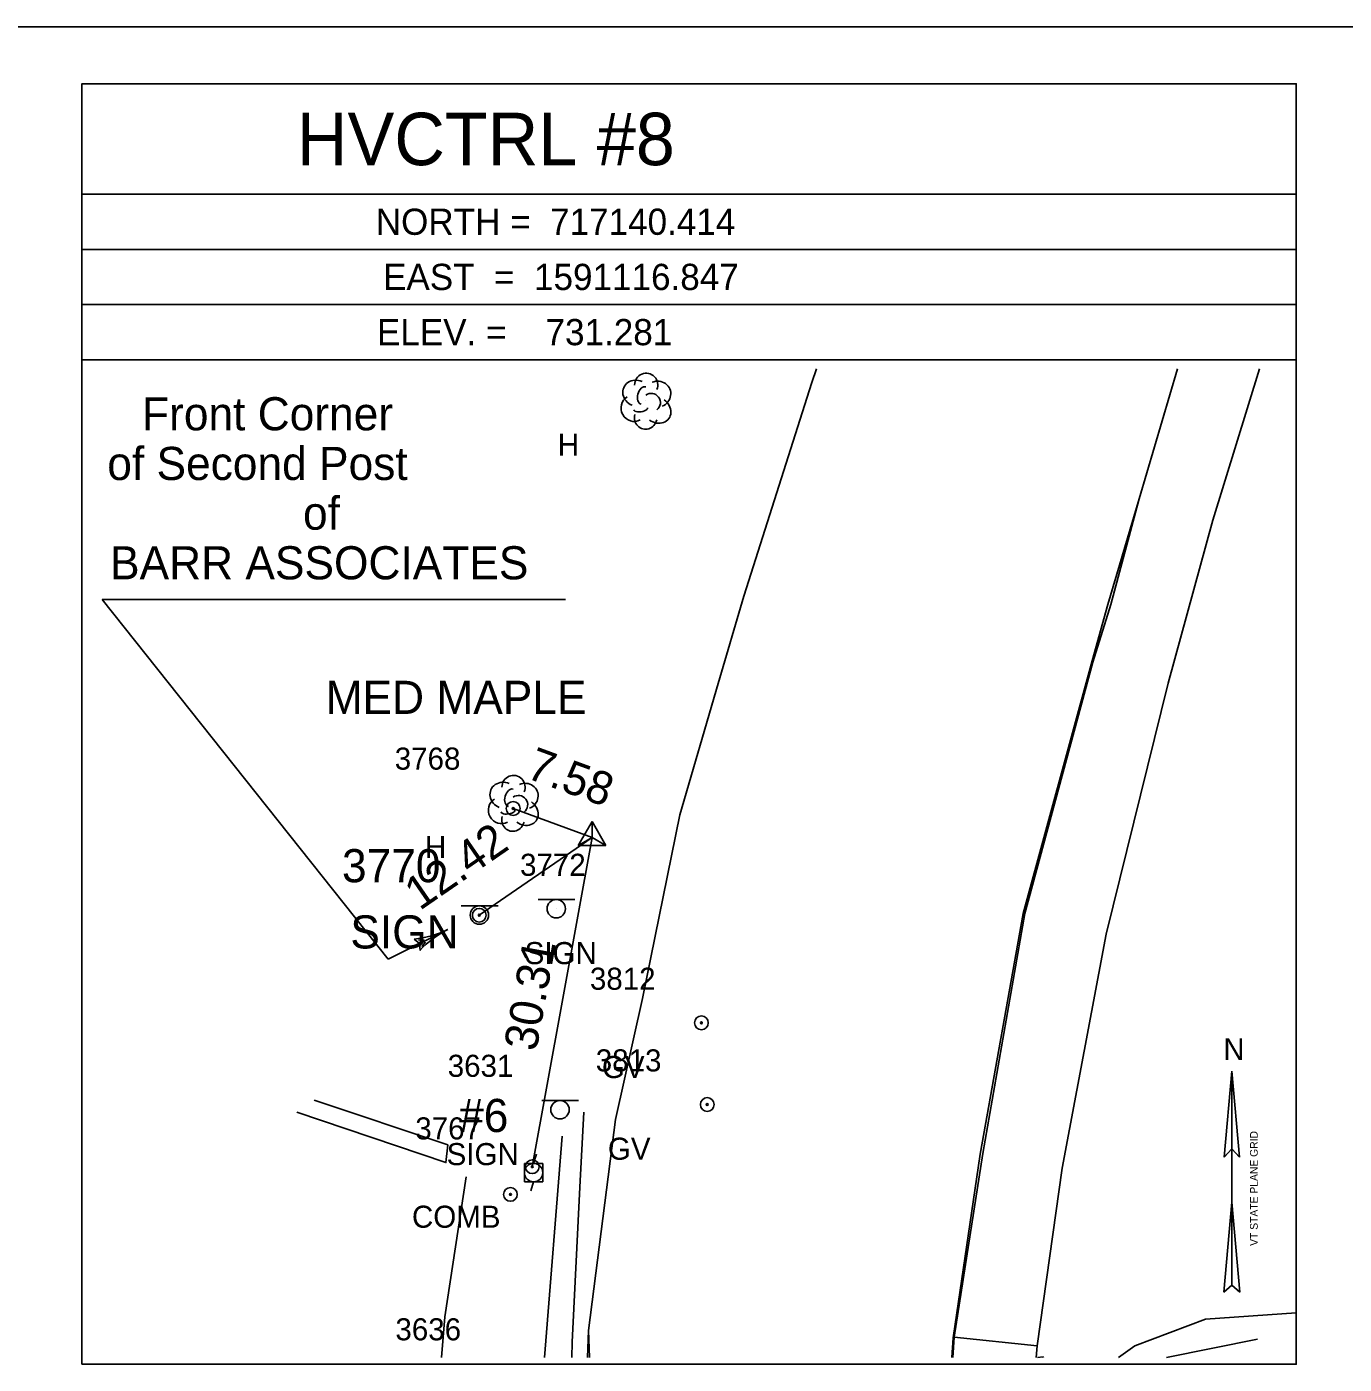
# Model space of a CAD drawing. Extents: x 1586965 to 1590952, y 716317 to 720029.
# Drawn here: x 1590582.2 to 1590701.5, y 716489.9 to 716611 of the extents above; entities that cross this region are included whole.
import ezdxf

# ---------------------------------------------------------------- set-up
doc = ezdxf.new("R2010")
doc.units = 0
for name, color, linetype in [('CBP', 7, 'Continuous'), ('CPSM', 7, 'Continuous'), ('Default', 7, 'Continuous'), ('L_A', 7, 'Continuous'), ('L_C', 7, 'Continuous'), ('L_I', 7, 'Continuous'), ('LAHR', 7, 'Continuous'), ('LAPB', 7, 'Continuous'), ('LTD', 7, 'Continuous'), ('LW', 7, 'Continuous'), ('MPIR', 7, 'Continuous'), ('NBL2', 7, 'Continuous'), ('NNA_P', 7, 'Continuous'), ('PET', 7, 'Continuous'), ('PSP', 7, 'Continuous'), ('RC', 7, 'Continuous'), ('RDG', 7, 'Continuous'), ('RDP', 7, 'Continuous'), ('RSW', 7, 'Continuous'), ('S_A', 7, 'Continuous'), ('S_C', 7, 'Continuous'), ('S_I', 7, 'Continuous'), ('SSGN', 7, 'Continuous'), ('U_A', 7, 'Continuous'), ('U_C', 7, 'Continuous'), ('U_I', 7, 'Continuous'), ('UP', 7, 'Continuous'), ('UWV', 7, 'Continuous')]:
    doc.layers.add(name, color=color, linetype=linetype)

msp = doc.modelspace()

# ---------------------------------------------------------------- linework, layer by layer
at = {"layer": 'CBP'}
for centre, radius in [((1590626.26, 716540.21), 0.625), ((1590626.26, 716540.21), 0.0833), ((1590623.19, 716530.54), 0.625), ((1590623.19, 716530.54), 0.0833), ((1590627.99, 716507.76), 0.625), ((1590627.99, 716507.76), 0.0833)]:
    msp.add_circle(centre, radius, dxfattribs=at)
at = {"layer": 'CPSM'}
for p, q in [((1590632.15, 716536.87), (1590633.4, 716539.03)), ((1590634.65, 716536.87), (1590633.4, 716539.03)), ((1590633.4, 716537.59), (1590633.4, 716539.03)), ((1590632.15, 716536.87), (1590633.4, 716537.59)), ((1590633.4, 716537.59), (1590633.4, 716537.59)), ((1590633.4, 716537.59), (1590634.65, 716536.87)), ((1590632.15, 716536.87), (1590634.65, 716536.87))]:
    msp.add_line(p, q, dxfattribs=at)
at = {"layer": 'Default'}
for p, q in [((1590630.99, 716559.15), (1590589.02, 716559.15)), ((1590589.02, 716559.15), (1590614.93, 716526.55)), ((1590626.26, 716540.21), (1590633.4, 716537.59)), ((1590633.4, 716537.59), (1590623.19, 716530.54)), ((1590633.4, 716537.59), (1590627.99, 716507.76)), ((1590614.93, 716526.55), (1590620.33, 716529.25)), ((1590617.3, 716528.38), (1590617.78, 716527.97)), ((1590617.67, 716528.29), (1590618.2, 716528.32)), ((1590617.82, 716527.35), (1590617.78, 716527.97)), ((1590617.97, 716527.7), (1590618.31, 716528.1))]:
    msp.add_line(p, q, dxfattribs=at)
for centre, start, end in [((1590616.49, 716536.91), 275.388, 296.5751), ((1590624.16, 716521.59), 116.5826, 137.7697)]:
    msp.add_arc(centre, 8.57, start, end, dxfattribs=at)
at = {"layer": 'LAHR'}
msp.add_lwpolyline([(1590630.69, 716510.54), (1590629.1, 716490.49)], dxfattribs=at)
at = {"layer": 'LAPB'}
msp.add_lwpolyline([(1590693.69, 716492.13), (1590685.45, 716490.49)], dxfattribs=at)
at = {"layer": 'LTD'}
for p, q in [((1590638.27, 716577.16), (1590638.27, 716577.16)), ((1590638.27, 716577.16), (1590638.27, 716577.16)), ((1590626.25, 716540.73), (1590626.25, 716540.73)), ((1590626.25, 716540.73), (1590626.25, 716540.73))]:
    msp.add_line(p, q, dxfattribs=at)
for centre in [(1590638.31, 716578.59), (1590626.29, 716542.16)]:
    msp.add_arc(centre, 1.05, 335.5272, 180.9563, dxfattribs=at)
for centre, major_axis, ratio, start_param, end_param in [((1590637.48, 716577.82), (1.21, -0.51), 0.895232, 1.570796, 4.712389), ((1590638.06, 716577.62), (-0.208, -0.792), 0.645439, 3.141593, 6.283185), ((1590639.31, 716577.74), (-1.14, -0.48), 0.949671, 1.570796, 4.712389), ((1590637.18, 716576.45), (0.58, -1.04), 0.959034, 3.141593, 6.283185), ((1590638.77, 716576.99), (-0.5, 0.667), 0.989748, 3.141593, 6.283185), ((1590637.81, 716576.41), (-0.625, -0.083), 0.423636, 0, 3.141593), ((1590639.27, 716576.32), (-1.09, 0.79), 0.841452, 1.570796, 4.712389), ((1590638.27, 716575.66), (0.26, 1.06), 0.942809, 1.570796, 4.712389), ((1590625.45, 716541.39), (1.21, -0.51), 0.895232, 1.570796, 4.712389), ((1590627.29, 716541.31), (-1.14, -0.48), 0.949671, 1.570796, 4.712389), ((1590625.16, 716540.02), (0.58, -1.04), 0.959034, 3.141593, 6.283185), ((1590626.04, 716541.18), (-0.208, -0.792), 0.645439, 3.141593, 6.283185), ((1590626.75, 716540.56), (-0.5, 0.667), 0.989748, 3.141593, 6.283185), ((1590625.79, 716539.98), (-0.625, -0.083), 0.423636, 0, 3.141593), ((1590627.25, 716539.89), (-1.09, 0.79), 0.841452, 1.570796, 4.712389), ((1590626.25, 716539.23), (0.26, 1.06), 0.942809, 1.570796, 4.712389)]:
    msp.add_ellipse(centre, major_axis=major_axis, ratio=ratio, start_param=start_param, end_param=end_param, dxfattribs=at)
at = {"layer": 'LW'}
for points in [[(1590608.24, 716513.78), (1590620.33, 716509.73), (1590620.16, 716508.14), (1590606.65, 716512.69)], [(1590631.58, 716490.49), (1590631.59, 716491.87), (1590632.29, 716505.92), (1590632.66, 716512.7)]]:
    msp.add_lwpolyline(points, dxfattribs=at)
at = {"layer": 'MPIR'}
for radius in [0.625, 0.0833]:
    msp.add_circle((1590626.01, 716505.25), radius, dxfattribs=at)
at = {"layer": 'NBL2'}
for p, q in [((1590312.19, 716611.03), (1590952.19, 716611.03)), ((1590697.19, 716595.86), (1590587.19, 716595.86)), ((1590697.19, 716590.86), (1590587.19, 716590.86)), ((1590697.19, 716585.86), (1590587.19, 716585.86)), ((1590697.19, 716580.86), (1590587.19, 716580.86))]:
    msp.add_line(p, q, dxfattribs=at)
msp.add_lwpolyline([(1590587.19, 716489.86), (1590697.19, 716489.86), (1590697.19, 716605.86), (1590587.19, 716605.86)], close=True, dxfattribs=at)
at = {"layer": 'NNA_P'}
for p, q in [((1590690.66, 716508.61), (1590691.36, 716516.41)), ((1590691.36, 716497.03), (1590691.36, 716516.41)), ((1590692.05, 716508.61), (1590691.36, 716516.41)), ((1590690.66, 716508.61), (1590691.36, 716509.38)), ((1590692.05, 716508.61), (1590691.36, 716509.38)), ((1590691.36, 716504.56), (1590690.64, 716496.39)), ((1590691.36, 716504.56), (1590692.08, 716496.39)), ((1590691.36, 716497.03), (1590690.64, 716496.39)), ((1590691.36, 716497.03), (1590692.08, 716496.39))]:
    msp.add_line(p, q, dxfattribs=at)
at = {"layer": 'PET'}
for points in [[(1590653.75, 716580.04), (1590653.31, 716578.79), (1590647.14, 716559.44), (1590644.84, 716551.53)], [(1590666.01, 716490.49), (1590666.12, 716492.26), (1590668.55, 716508.9), (1590672.46, 716530.71), (1590678.7, 716553.58), (1590680.14, 716558.69), (1590682.98, 716568.25), (1590686.44, 716580.04)], [(1590644.84, 716551.53), (1590641.37, 716539.63), (1590637.97, 716523.01)], [(1590633.16, 716490.49), (1590633.09, 716492.92), (1590635.54, 716512.05), (1590637.97, 716523.01)]]:
    msp.add_lwpolyline(points, dxfattribs=at)
at = {"layer": 'PSP'}
msp.add_lwpolyline([(1590632.98, 716490.49), (1590633.09, 716492.92)], dxfattribs=at)
at = {"layer": 'RC'}
msp.add_lwpolyline([(1590666.1, 716490.49), (1590666.22, 716492.33), (1590668.81, 716508.97), (1590672.61, 716530.7), (1590678.77, 716553.47), (1590680.4, 716558.69), (1590682.98, 716568.25)], dxfattribs=at)
at = {"layer": 'RDG'}
msp.add_lwpolyline([(1590622.01, 716506.83), (1590620.08, 716494.16), (1590619.78, 716490.49)], dxfattribs=at)
at = {"layer": 'RDP'}
for points in [[(1590681.1, 716490.49), (1590682.58, 716491.54), (1590688.98, 716493.96), (1590697.19, 716494.53)], [(1590673.75, 716490.49), (1590674.27, 716490.55), (1590674.31, 716490.49)]]:
    msp.add_lwpolyline(points, dxfattribs=at)
at = {"layer": 'RSW'}
for points in [[(1590673.72, 716491.53), (1590675.98, 716507.62), (1590679.98, 716528.84), (1590685.6, 716551.57), (1590689.63, 716566.32), (1590693.87, 716580.04)], [(1590673.64, 716490.49), (1590673.72, 716491.53), (1590666.22, 716492.33)]]:
    msp.add_lwpolyline(points, dxfattribs=at)
at = {"layer": 'SSGN'}
for p, q in [((1590621.55, 716531.39), (1590624.89, 716531.39)), ((1590628.51, 716531.96), (1590631.85, 716531.96)), ((1590623.2, 716530.55), (1590623.2, 716530.55)), ((1590630.16, 716531.13), (1590630.16, 716531.13)), ((1590628.86, 716513.76), (1590632.19, 716513.76)), ((1590630.5, 716512.92), (1590630.5, 716512.92))]:
    msp.add_line(p, q, dxfattribs=at)
for centre in [(1590623.2, 716530.55), (1590630.16, 716531.13), (1590630.5, 716512.92)]:
    msp.add_circle(centre, 0.833, dxfattribs=at)
at = {"layer": 'UP'}
for p, q in [((1590628.36, 716508.9), (1590628.11, 716508.06)), ((1590627.28, 716506.4), (1590627.28, 716508.06)), ((1590627.28, 716508.06), (1590628.94, 716508.06)), ((1590628.11, 716507.23), (1590628.11, 716507.23)), ((1590628.94, 716508.06), (1590628.94, 716506.4)), ((1590628.94, 716506.4), (1590627.28, 716506.4)), ((1590627.86, 716505.56), (1590628.11, 716506.4))]:
    msp.add_line(p, q, dxfattribs=at)
msp.add_circle((1590628.11, 716507.23), 0.833, dxfattribs=at)
at = {"layer": 'UWV'}
for centre, radius in [((1590643.31, 716520.79), 0.625), ((1590643.31, 716520.79), 0.0833), ((1590643.84, 716513.39), 0.625), ((1590643.84, 716513.39), 0.0833)]:
    msp.add_circle(centre, radius, dxfattribs=at)

# ---------------------------------------------------------------- texts
at = {"layer": 'Default'}
for s, rotation, p in [('7.58', 339.8331, (1590627.31, 716543.02)), ('12.42', 34.6133, (1590617.79, 716530.91)), ('30.31', 79.7205, (1590628.35, 716518.13))]:
    msp.add_text(s, height=3, rotation=rotation, dxfattribs=at).set_placement(p)
at = {"layer": 'L_A'}
for p in [(1590630.29, 716572.16), (1590618.27, 716535.73)]:
    msp.add_text('H', height=2, dxfattribs=at).set_placement(p)
at = {"layer": 'L_C'}
msp.add_text('MED MAPLE', height=3, dxfattribs=at).set_placement((1590609.27, 716548.78))
at = {"layer": 'L_I'}
for s, p in [('3768', (1590615.53, 716543.73)), ('3636', (1590615.59, 716492.03))]:
    msp.add_text(s, height=2, dxfattribs=at).set_placement(p)
at = {"layer": 'NBL2'}
for s, height, p in [('     HVCTRL #8     ', 4.75, (1590597.84, 716598.49)), ('NORTH =  717140.414 ', 2.375, (1590613.81, 716592.18)), ('EAST  =  1591116.847', 2.375, (1590614.47, 716587.18)), ('ELEV. =    731.281  ', 2.375, (1590613.92, 716582.18))]:
    msp.add_text(s, height=height, dxfattribs=at).set_placement(p)
at = {"layer": 'NNA_P'}
msp.add_text('N', height=1.97, dxfattribs=at).set_placement((1590690.6, 716517.42))
msp.add_text('VT STATE PLANE GRID', height=0.7, rotation=90.0204, dxfattribs=at).set_placement((1590693.71, 716500.59))
at = {"layer": 'S_A'}
for height, p in [(3, (1590611.51, 716527.53)), (2, (1590627.3, 716526.11)), (2, (1590620.23, 716507.9))]:
    msp.add_text('SIGN', height=height, dxfattribs=at).set_placement(p)
at = {"layer": 'S_C'}
for s, p in [('Front Corner', (1590592.64, 716574.47)), ('of Second Post', (1590589.49, 716569.97)), ('of', (1590607.22, 716565.47)), ('BARR ASSOCIATES', (1590589.74, 716560.97))]:
    msp.add_text(s, height=3, dxfattribs=at).set_placement(p)
at = {"layer": 'S_I'}
for s, height, p in [('3770', 3, (1590610.75, 716533.53)), ('3772', 2, (1590626.88, 716534.11)), ('3631', 2, (1590620.33, 716515.9))]:
    msp.add_text(s, height=height, dxfattribs=at).set_placement(p)
at = {"layer": 'U_A'}
for s, p in [('GV', (1590634.3, 716515.79)), ('GV', (1590634.84, 716508.39)), ('COMB', (1590617.09, 716502.23))]:
    msp.add_text(s, height=2, dxfattribs=at).set_placement(p)
at = {"layer": 'U_C'}
msp.add_text('#6', height=3, dxfattribs=at).set_placement((1590621.36, 716510.9))
at = {"layer": 'U_I'}
for s, p in [('3812', (1590633.21, 716523.79)), ('3813', (1590633.74, 716516.39)), ('3767', (1590617.39, 716510.23))]:
    msp.add_text(s, height=2, dxfattribs=at).set_placement(p)

doc.saveas('drawing.dxf')
